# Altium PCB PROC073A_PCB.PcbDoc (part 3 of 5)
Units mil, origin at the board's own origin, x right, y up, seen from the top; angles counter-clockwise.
Board outline 2165.35 x 2165.35 mil, 6 copper layers (Top Layer, L2, L3, L4, L5, Bottom Layer), stack 55.77 mil thick; 284 components, 233 nets, 945 pads, 1419 vias.
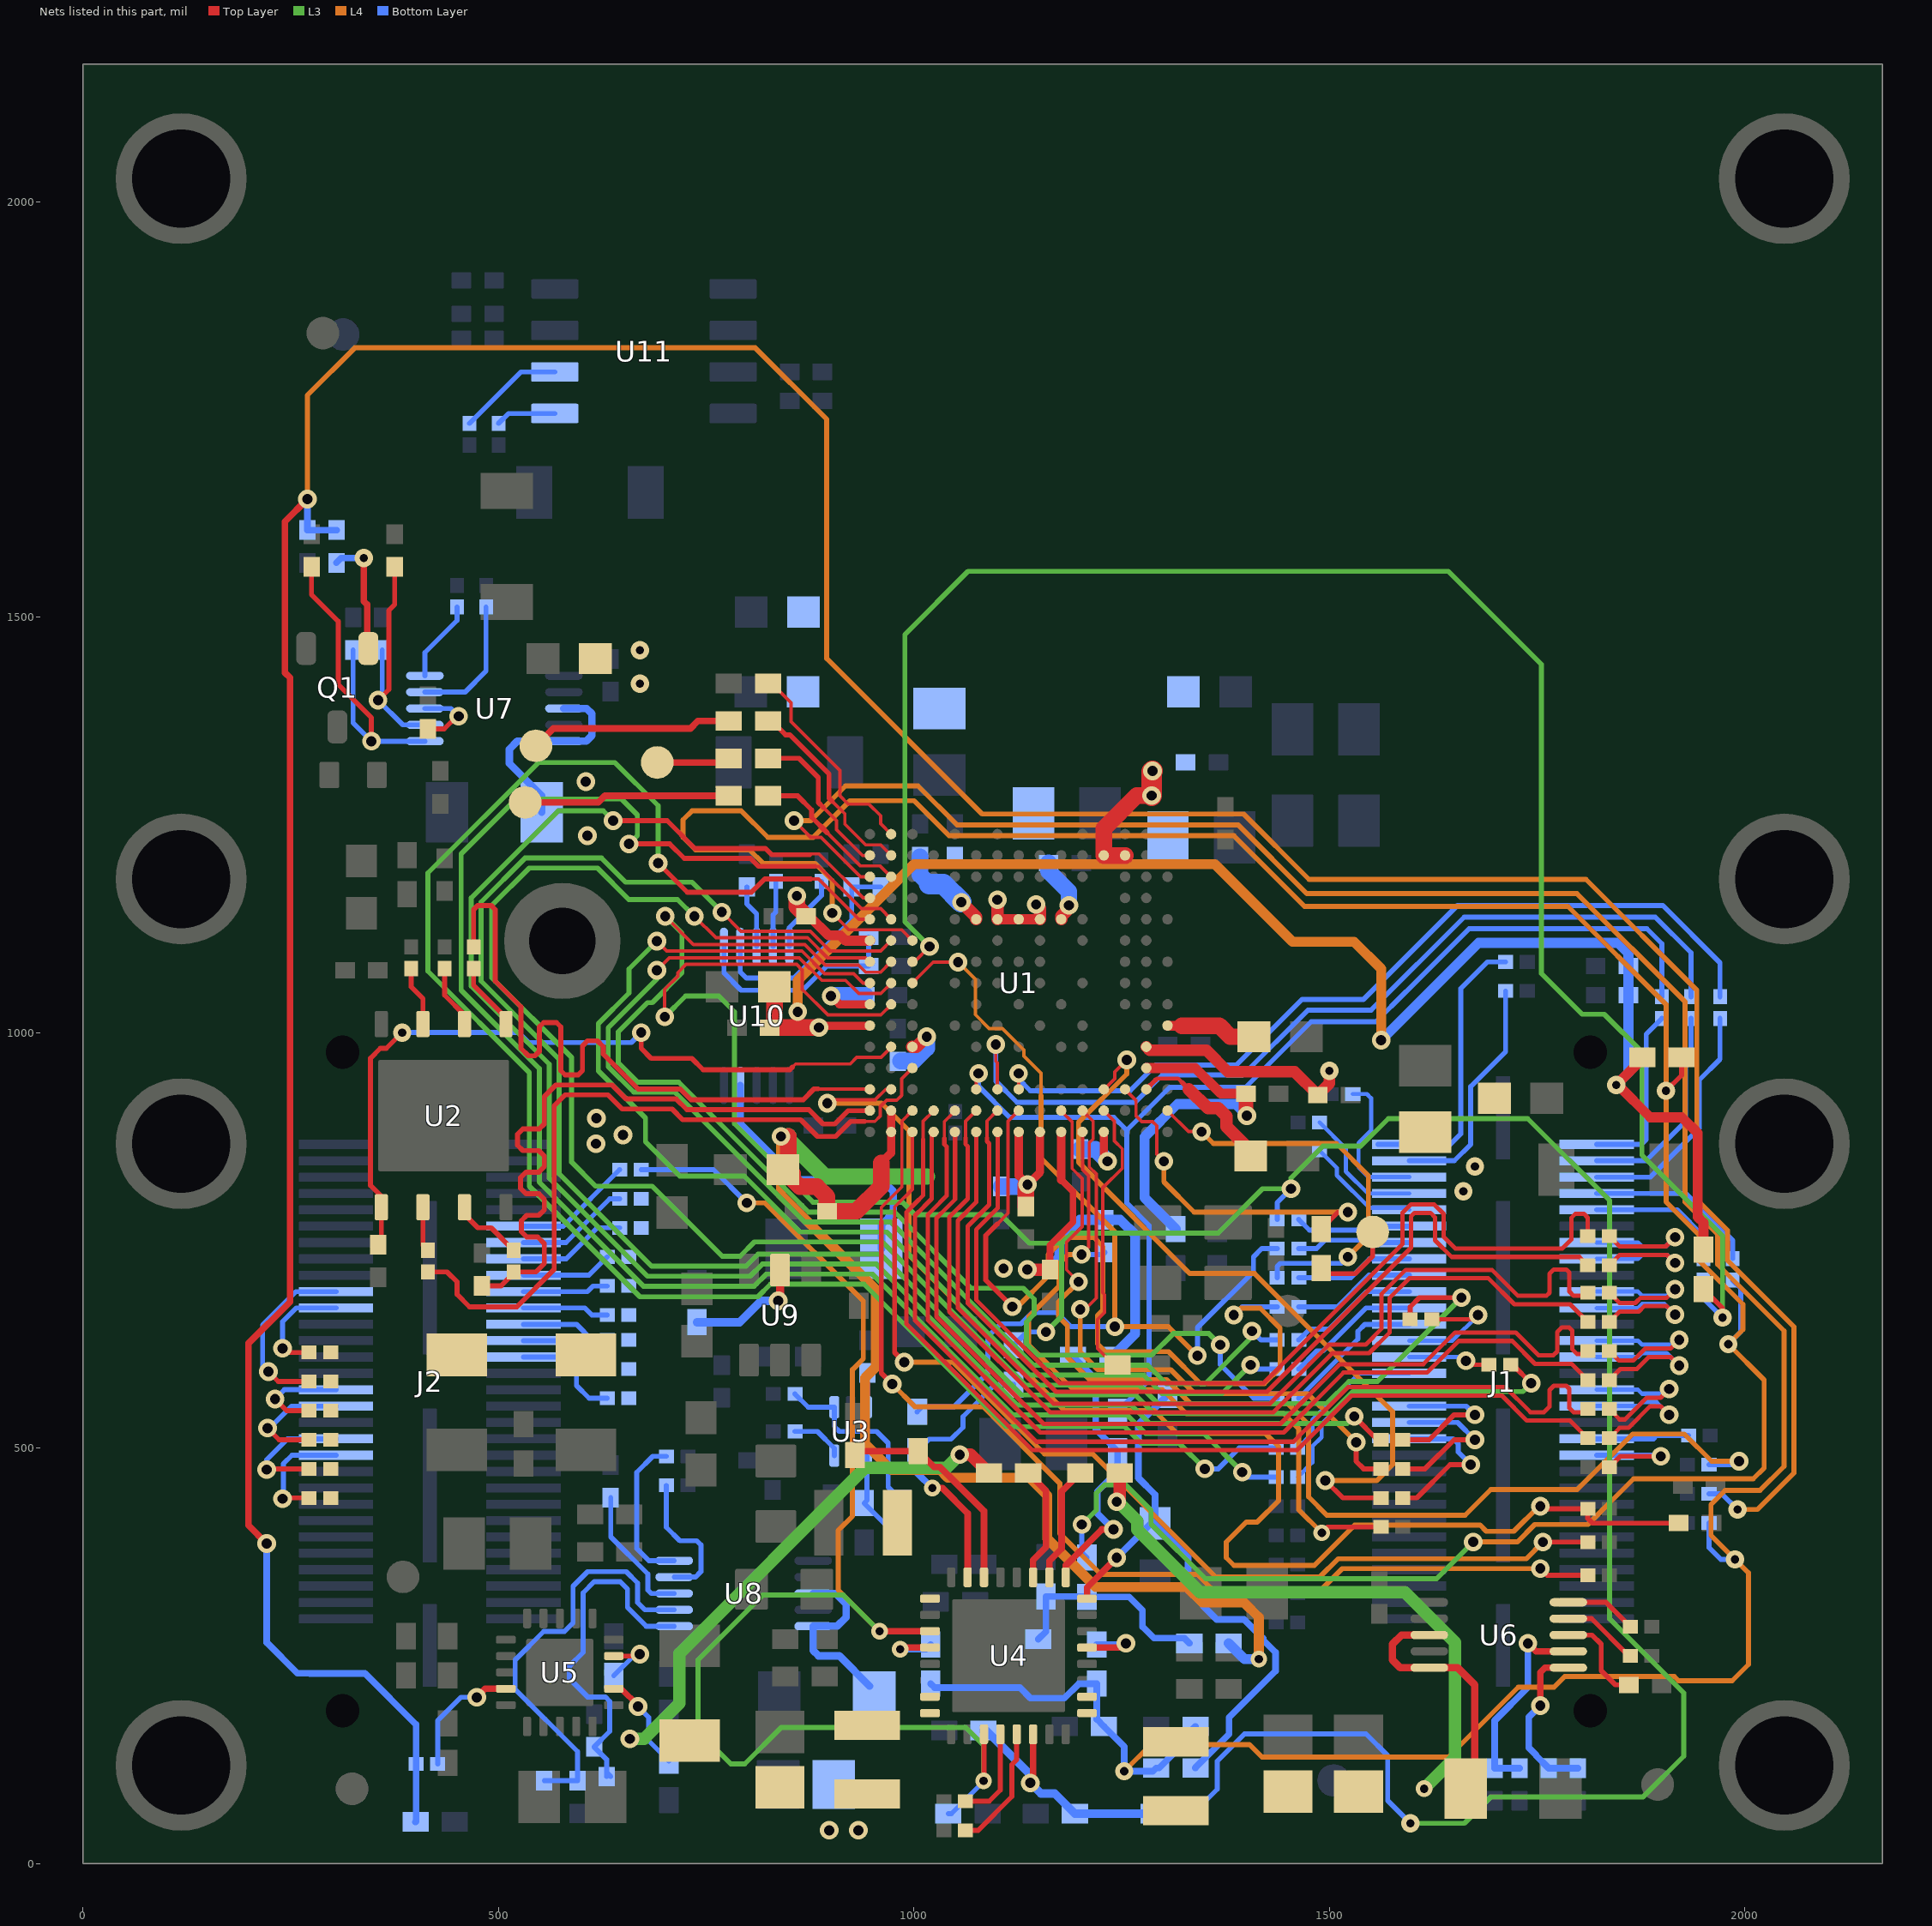
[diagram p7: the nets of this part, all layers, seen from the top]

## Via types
v1: diameter 13.77/15.74 (per signal layer), hole 5.9, Top Layer to L2, tented both sides, 894 vias
v2: diameter 22.4, hole 12.2, Top Layer to Bottom Layer, tented both sides, 340 vias
v3: diameter 13.78/15.75 (per signal layer), hole 5.9, Top Layer to L2, tented both sides, 72 vias
v4: diameter 22, hole 10, Top Layer to Bottom Layer, tented both sides, 54 vias
v5: diameter 20, hole 10, Top Layer to Bottom Layer, tented both sides, 35 vias
v6: diameter 13.77/15.74 (per signal layer), hole 5.9, Top Layer to L2, tented top, 14 vias
v7: diameter 19.68, hole 7.87, Top Layer to Bottom Layer, tented both sides, 9 vias
v8: diameter 13.78/15.75 (per signal layer), hole 5.9, Top Layer to L2, tented top, 1 vias

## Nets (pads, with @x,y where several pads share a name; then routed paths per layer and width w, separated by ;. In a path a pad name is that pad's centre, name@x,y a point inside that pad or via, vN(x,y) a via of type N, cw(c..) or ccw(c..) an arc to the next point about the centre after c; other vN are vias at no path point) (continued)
NetJ1_22: J1.22 R36.1 | length 145.2
  Top Layer w6: R36.1@1836.74,476.85 1849.89,490 v2(1898.74,490)
  Bottom Layer w6: J1.22@1821.54,491.42 1897.32,491.42 v2(1898.74,490)
NetJ1_23: J1.23 R11.2 | length 191.3
  Top Layer w6: R11.2@1587.99,440 1605,440 1645,480 v2(1670,480)
  Bottom Layer w6: J1.23@1595.95,511.1 1648.7,511.1 1654.8,505 1654.8,495.2 v2(1670,480)
NetJ1_24: J1.24 R16.1 | length 112.1
  Bottom Layer w6: J1.24@1821.54,511.1 1890,511.1 1893.9,515 R16.1@1932.01,515
NetJ1_25: J1.25 R12.1 | length 189.2
  Top Layer w6: R12.1@1587.99,475 1615,475 1650,510 v2(1675,510)
  Bottom Layer w6: J1.25@1595.95,530.79 1654.21,530.79 v2(1675,510)
NetJ1_27: J1.27 R18.2 | length 182.8
  Top Layer w6: R18.2@1587.99,510 1620,510 1650,540 v2(1675,540)
  Bottom Layer w6: J1.27@1595.95,550.47 1664.53,550.47 v2(1675,540)
NetJ1_28: J1.28 R22.1 | length 188
  Top Layer w5.2: R22.1@1836.74,511.85 1849.14,524.25 1859.78,524.25 1885.93,550.4 1898.47,550.4 v2(1908.87,540)
  Bottom Layer w5.2: J1.28@1821.54,550.47 1871.32,550.47 1876.07,555.21 1893.65,555.21 v2(1908.87,540)
NetJ1_29: J1.29 R19.2 | length 198.4
  Bottom Layer w5: R19.2@1461.74,465 1479.39,482.65 1479.39,501.82 1490.59,513.02 1490.59,529.01 1531.74,570.16 J1.29@1595.95,570.16
NetJ1_30: J1.30 R24.1 | length 184
  Top Layer w5.2: R24.1@1836.74,546.85 1849.14,534.45 1855.55,534.45 1881.7,560.6 1898.47,560.6 v2(1908.87,571)
  Bottom Layer w5.2: J1.30@1821.54,570.16 1871.32,570.16 1876.07,565.41 1903.28,565.41 v2(1908.87,571)
NetJ1_31: J1.31 R20.2 | length 180.8
  Bottom Layer w5: R20.2@1461.74,500 1479.39,517.65 1479.39,533.65 1535.58,589.84 J1.31@1595.95,589.84
NetJ1_33: J1.33 R21.2 | length 100
  Top Layer w5.2: v2(1664.21,605) 1669.22,600 R21.2@1692.01,600
  Bottom Layer w5: J1.33@1595.95,609.53 1659.69,609.53 v2(1664.21,605)
NetJ1_34: J1.34 R30.1 | length 207.5
  Top Layer w5.2: R30.1@1836.74,581.85 1850.02,595.13 1869.81,595.13 1884.22,609.55 1910.47,609.55 v2(1920.87,599.14)
  Bottom Layer w5.2: J1.34@1821.54,609.53 1871.32,609.53 1876.07,614.27 1905.74,614.27 v2(1920.87,599.14)
NetJ1_35: J1.35 R23.2 | length 153.4
  Top Layer w5.2: R23.2@1622.99,655 1673.74,655 v2(1678.74,660)
  Bottom Layer w5: J1.35@1595.95,629.21 1647.95,629.21 v2(1678.74,660)
NetJ1_36: J1.36 R32.1 | length 202.8
  Top Layer w5.2: R32.1@1836.74,616.85 1848.25,605.33 1865.59,605.33 1880,619.75 1910.47,619.75 v2(1920.87,630.14)
  Bottom Layer w5.2: J1.36@1821.54,629.21 1871.32,629.21 1876.07,624.47 1915.19,624.47 v2(1920.87,630.14)
NetJ1_37: J1.37 R26.2 | length 175.2
  Bottom Layer w6: R26.2@1462.99,560 1534.23,631.23 1534.23,640.48 1542.64,648.9 J1.37@1595.95,648.9
NetJ1_39: J1.39 R27.2 | length 163.4
  Bottom Layer w6: R27.2@1462.99,595 1484.92,616.93 1492.27,616.93 1543.92,668.58 J1.39@1595.95,668.58
NetJ1_40: J1.40 R33.1 | length 192.7
  Top Layer w5.2: R33.1@1836.74,651.85 1849.14,664.25 1872.17,664.25 1878.64,670.72 1905.79,670.72 v2(1915.87,660.65)
  Bottom Layer w5.2: J1.40@1821.54,668.58 1871.32,668.58 1876.07,673.32 1903.19,673.32 v2(1915.87,660.65)
NetJ1_41: J1.41 R28.2 | length 208.6
  Bottom Layer w5: 1544.74,688.01 1544.74,688.27 J1.41@1595.95,688.27
  Bottom Layer w6: R28.2@1462.99,630 1475.91,642.92 1499.23,642.92 1544.58,688.27 J1.41@1595.95,688.27
NetJ1_42: J1.42 R35.1 | length 190.5
  Top Layer w5.2: R35.1@1836.74,686.85 1849.14,674.45 1867.94,674.45 1870.05,676.56 1874.42,680.92 1905.79,680.92 v2(1915.87,691)
  Bottom Layer w5.2: J1.42@1821.54,688.27 1871.32,688.27 1876.07,683.52 1908.39,683.52 v2(1915.87,691)
NetJ1_43: J1.43 R60.1 | length 148.7
  Bottom Layer w6: R60.1@1462.99,670 1509.34,670 1547.29,707.95 J1.43@1595.95,707.95
NetJ1_45: J1.45 R61.1 | length 142.3
  Bottom Layer w6: R61.1@1462.99,705 1525.57,705 1548.21,727.64 J1.45@1595.95,727.64
NetJ1_46: J1.46 R39.1 | length 188.5
  Top Layer w5.2: R39.1@1836.74,720 1849.13,732.4 1906.26,732.4 v2(1915.87,722.8)
  Bottom Layer w5.2: J1.46@1821.54,727.64 1871.32,727.64 1876.07,732.38 1906.28,732.38 v2(1915.87,722.8)
NetJ1_47: J1.47 R62.1 | length 138.4
  Bottom Layer w6: R62.1@1462.99,740 1484.33,740 1494.53,750.2 1536.45,750.2 1539.33,747.32 J1.47@1595.95,747.32
NetJ1_48: J1.48 R41.1 | length 189.8
  Top Layer w5.2: R41.1@1836.74,755 1849.13,742.6 1904.67,742.6 v2(1915.87,753.8)
  Bottom Layer w5.2: J1.48@1821.54,747.32 1871.32,747.32 1876.07,742.58 1904.65,742.58 v2(1915.87,753.8)
NetJ1_49: J1.49 R63.1 | length 140.2
  Bottom Layer w6: R63.1@1462.99,775 1475.79,762.2 1538.17,762.2 1542.98,767.01 J1.49@1595.95,767.01
NetJ1_51: J1.51 R64.1 | length 142.9
  Bottom Layer w5: R64.1@1487.99,858 1508.75,837.24 1508.75,828.27 1547.74,789.28 1547.74,789 1593.64,789 J1.51@1595.95,786.69
NetJ1_52: J1.52 R58.1 | length 168.6
  Bottom Layer w6: J1.52@1821.54,786.69 1918.31,786.69 1950,755 R58.1@1950,727.99
NetJ1_53: J1.53 R34.2 | length 159.5
  Bottom Layer w5: R34.2@1487.99,892 1519.75,860.24 1519.75,832.83 1546.2,806.38 J1.53@1595.95,806.38
NetJ1_54: J1.54 R59.1 | length 208.8
  Bottom Layer w6: J1.54@1821.54,806.38 1928.62,806.38 1985,750 R59.1@1985,727.99
NetJ1_55: J1.55 R37.2 | length 179.1
  Bottom Layer w5: R37.2@1527.99,926 1545,926 1550,921 1550,882 1535,867 1535,838.06 1547,826.06 J1.55@1595.95,826.06
NetJ1_56: J1.56 R65.2 | length 290.2
  Bottom Layer w6: J1.56@1821.54,826.06 1886.06,826.06 1944.81,884.81 1944.81,942.79 1970,967.98 R65.2@1970,1017.01
NetJ1_57: J1.57 R38.2 | length 284.2
  Bottom Layer w5.98: J1.57@1595.95,845.75 1650.36,845.75 1670,865.39 1670,935 1712.01,977.01 R38.2@1712.01,1050
NetJ1_58: J1.58 R66.1 | length 253
  Bottom Layer w6: J1.58@1821.54,845.75 1880.86,845.75 1928.25,893.14 1928.25,968.32 1935,975.07 R66.1@1935,1017.01
NetJ1_59: J1.59 R40.2 | length 347.2
  Bottom Layer w5.98: J1.59@1558.31,865.43 1645.43,865.43 1658.01,878.01 1658.01,1053.01 1690,1085 R40.2@1712.01,1085
NetJ1_60: J1.60 R67.1 | length 215.6
  Bottom Layer w6: J1.60@1821.54,865.43 1875.43,865.43 1881.13,871.13 1881.13,998.14 R67.1@1900,1017.01
NetJ2_11: J2.11 R140.2 | length 143.9
  Bottom Layer w6: J2.11@530.04,767.01 577.76,767.01 R140.2@645.75,835
NetJ2_13: J2.13 R124.2 | length 137.5
  Bottom Layer w6: J2.13@530.04,747.32 581.07,747.32 633.74,800 R124.2@645.75,800
NetJ2_15: J2.15 R125.2 | length 131.2
  Bottom Layer w6: J2.15@530.04,727.64 581.38,727.64 618.74,765 R125.2@645.75,765
NetJ2_17: J2.17 R126.2 | length 109.8
  Bottom Layer w6: J2.17@530.04,707.95 608.7,707.95 R126.2@630.75,730
NetJ2_19: J2.19 R127.2 | length 103.5
  Bottom Layer w6: J2.19@530.04,688.27 607.01,688.27 613.74,695 R127.2@630.75,695
NetJ2_20: J2.20 R131.1 | length 218.2
  Top Layer w6: v2(223,592) 235,580 R131.1@272.01,580
  Bottom Layer w6: v2(223,592) 216,599 216,648.27 256,688.27 J2.20@304.44,688.27
NetJ2_21: J2.21 R128.2 | length 104.3
  Bottom Layer w6: J2.21@530.04,668.58 603.74,668.58 612.33,660 R128.2@630.75,660
NetJ2_22: J2.22 R133.1 | length 137.4
  Top Layer w6: v2(240,620) 245,615 R133.1@272.01,615
  Bottom Layer w6: v2(240,620) 240,652 256.58,668.58 J2.22@304.44,668.58
NetJ2_23: J2.23 R129.2 | length 108.5
  Bottom Layer w6: J2.23@530.04,648.9 593.74,648.9 612.64,630 R129.2@630.75,630
NetJ2_25: J2.25 R130.2 | length 114.9
  Bottom Layer w6: J2.25@530.04,629.21 583.67,629.21 617.88,595 R130.2@630.75,595
NetJ2_27: J2.27 R132.2 | length 135.7
  Bottom Layer w6: J2.27@530.04,609.53 584.21,609.53 593.74,600 593.74,575.29 609.03,560 R132.2@630.75,560
NetJ2_32: J2.32 R134.1 | length 124.9
  Top Layer w6: v2(231,559) 245,545 R134.1@272.01,545
  Bottom Layer w6: v2(231,559) 242.16,570.16 J2.32@304.44,570.16
NetJ2_34: J2.34 R135.1 | length 149.2
  Top Layer w6: v2(222,524) 236,510 R135.1@272.01,510
  Bottom Layer w6: v2(222,524) 224.57,524 251.04,550.47 J2.34@304.44,550.47
NetJ2_38: J2.38 R136.1 | length 157.3
  Top Layer w6: v2(221,474) 222,475 R136.1@272.01,475
  Bottom Layer w6: v2(221,474) 221,486 246,511 304.34,511 J2.38@304.44,511.1
NetJ2_40: J2.40 R137.1 | length 142.6
  Top Layer w6: v2(240,439) 241,440 R137.1@272.01,440
  Bottom Layer w6: v2(240,439) 241.2,440.2 241.2,481.2 251.42,491.42 J2.40@304.44,491.42
NetL4_1: L4.1 U4.25 U4.26
NetL5_1: L5.1 U4.15 U4.16
NetL6_2: L6.2 U4.9
NetQ1_1: Q1.1 R79.2 | length 146.3
  Top Layer w7.87: v4(338,1571) 338,1519 342,1515
  Top Layer w8: 342,1515 342,1463.64 Q1.1@343.4,1462.24
  Bottom Layer w7.87: R79.2@305,1565.31 310.68,1571 v4(338,1571)
NetR2_1: R2.1 R101.2 U6.2 | length 249.6
  Top Layer w8: v2(1738.74,265) 1748.43,255.31 U6.2@1787.4,255.32
  Bottom Layer w8: R2.1@1728.74,114.69 R101.2@1698.74,114.69 1698.74,172 1738.74,212 v2(1738.74,265)
NetR14_1: R14.1 R103.2 U6.1 | length 202
  Top Layer w8: v2(1753.74,190) 1753.74,230 1759.37,235.63 U6.1@1787.4,235.63
  Bottom Layer w8: v2(1753.74,190) 1739.8,176.06 1739.8,139.42 1748.58,130.64 1748.58,129.84 R14.1@1763.74,114.69 R103.2@1798.74,114.69
NetR25_1: R25.1 U6.5 | length 87.7
  Top Layer w6: U6.5@1788.03,315 U6.5@1787.4,314.37 1832.64,314.37 R25.1@1862.01,285
NetR29_1: R29.1 U6.4 | length 93.1
  Top Layer w6: U6.4@1787.4,294.69 1815.31,294.68 1860,250 R29.1@1862.01,250
NetR45_1: R45.1 U2.5 | length 82.9
  Top Layer w6: R45.1@470,1077.01 470,1057 509,1018 U2.5@509,1010.24
NetR46_2: R46.2 U2.2 | length 54.3
  Top Layer w6: U2.2@409,789.76 409,743.99 R46.2@415,737.99
NetR47_2: R47.2 U2.3 | length 85.6
  Top Layer w6: U2.3@459,789.76 459,781 475,765 490.99,765 R47.2@518,737.99
NetR48_1: R48.1 U2.6 | length 76.7
  Top Layer w6: R48.1@435,1077.01 435,1045 459,1021 U2.6@459,1010.24
NetR51_1: R51.1 U2.7 | length 72.6
  Top Layer w6: R51.1@395,1077.01 395,1055 409,1041 U2.7@409,1010.24
NetR54_1: R54.1 U3.3 | length 41.3
  Bottom Layer w6: U3.3@943.43,549.13 943.74,549.45 R54.1@943.74,590.32
NetR55_2: R55.2 U3.6 | length 64.6
  Bottom Layer w6: R55.2@856.74,520 883.74,520 904.06,499.68 U3.6@904.06,490.87
NetR56_2: R56.2 R151.1 U3.1 | length 229.3
  Bottom Layer w6: R56.2@856.74,565 872.6,549.13 U3.1@904.06,549.13 904.06,525.94 910,520 955,520 969,506 969,453 985,437 R151.1@985,433.62
NetR57_1: R57.1 R151.2 U3.4 | length 124.5
  Bottom Layer w6: U3.4@943.43,490.87 943.43,437.05 R57.1@940,433.62 985,388.62 R151.2@985,386.38
NetR69_1: R69.1 R122.2 R168.2 U4.32 | length 720.2
  Top Layer w8: U4.32@1208.23,318.9 1208.23,332.23 v2(1244,368)
  Bottom Layer w8: v2@1246.44,368 v2(1244,368) 1285.5,409.5 R122.2@1290,409.5 ; R69.1@1305,563.62 1270,528.62 1270,464 1290,444 R122.2@1290,409.5 ; R168.2@1338.62,115 1338.62,115.29 1379.17,155.83 1379.17,175.71 1435,231.54 1435,254.25 1420,269.25 1420,270.94 1397.17,293.77 1364.23,293.77 1329.91,328.09 1329.91,369.59 R122.2@1290,409.5
NetR72_2: R72.2 U1.P1 | length 260.2
  Top Layer w4.02: R72.2@824.21,1420 828.74,1420 851.87,1396.87 851.87,1374.3 910.74,1315.43 910.74,1285 920.91,1274.83 945.93,1274.83 959.85,1260.9 959.85,1251.33 U1.P1@972.43,1238.75 U1.P1@972.64,1238.54
NetR73_2: R73.2 U1.P2 | length 239.8
  Top Layer w4: 901.74,1278.18 916.74,1263.18 916.74,1250.8 941.73,1225.81 959.78,1225.81 U1.P2@972.64,1212.95
  Top Layer w6: R73.2@824.21,1375 828.74,1375 845.37,1358.37 850.59,1358.37 897.74,1311.22 897.74,1282.18 901.74,1278.18
NetR74_2: R74.2 U1.P3 | length 193.7
  Top Layer w4: 895.24,1240.71 935.43,1200.52 959.48,1200.52 U1.P3@972.43,1187.57
  Top Layer w6: R74.2@824.21,1285 824.41,1284.8 859.94,1284.8 876.74,1268 876.74,1259.2 895.24,1240.71
NetR75_2: R75.2 U1.R2 | length 195
  Top Layer w4.02: 890.74,1270.97 906.73,1254.98 906.73,1244.34 938.12,1212.95 U1.R2@947.05,1212.95
  Top Layer w6: R75.2@824.21,1330 861.57,1330 884.74,1306.83 884.74,1276.97 890.74,1270.97
NetR76_2: R76.2 U1.C13 | length 414.8
  Top Layer w4: U1.C13@1254.13,931.45 1267.08,918.51 1267.08,899.86 1274.08,892.86 1287.08,892.86 1292.08,887.86 1292.08,853.51 v2(1300.59,845)
  Top Layer w6: R76.2@1490,763.62 1510.38,784 v2(1522,784)
  L4 w6: v2(1300.59,845) 1300.59,820.41 1337,784 v2(1522,784)
NetR77_2: R77.2 U1.D14 | length 341.7
  Top Layer w4: U1.D14@1228.54,905.86 1241,893.41 1241,869.59 1250.59,860 1250.59,836.54 1227.29,813.24 1227.29,686.63 1229.29,684.63 1229.29,663 1220.74,654.45 1220.74,620 1240.74,600 R77.2@1245.12,600
NetR82_1: R82.1 U4.2 | length 140.9
  Top Layer w8: U4.2@1162.96,344.49 1162.95,364.21 1177.74,379 1177.74,447.62 R82.1@1200.12,470
NetR83_1: R83.1 U5.12 | length 119.5
  Top Layer w7: U5.12@638.7,210.32 647.83,210.31 667.74,190.4 v2(667.74,189)
  Bottom Layer w6: v2(667.74,189) 680.83,175.91 680.83,147.79 R83.1@705,123.62
NetR84_1: R84.1 U4.3 | length 140.8
  Top Layer w8: R84.1@1137.36,470 1158.74,448.62 1158.74,380.8 1143.27,365.33 U4.3@1143.27,344.49
NetR86_1: R86.1 R93.2 R97.1 R167.1 | length 262
  Bottom Layer w8: R167.1@1149.62,270 1158.74,279.12 R97.1@1158.74,321.38 R93.2@1207.72,321.38 ; R93.2@1208.23,320.87 1258.86,320.87 1274.94,304.78 1274.94,285.07 1288.82,271.2 1325.18,271.2 R86.1@1331.38,265
NetR87_1: R87.1 R98.2 U4.6 | length 265.7
  Top Layer w8: R87.1@931,489.38 938,496.38 R98.2@1005,496.38 1024.08,477.3 1031.13,477.3 1084.21,424.21 U4.6@1084.22,344.49
NetR88_2: R88.2 U4.21 | length 150.2
  Top Layer w6: R88.2@1061.74,40 1077.18,40 1117.74,80.57 1117.74,119.16 1123.59,125 U4.21@1123.59,155.51
NetR89_2: R89.2 U4.20 | length 114.8
  Top Layer w6: R89.2@1061.74,75 1090.43,75 1103.9,88.47 U4.20@1103.9,155.51
NetR90_1: R90.1 U4.29 | length 84.5
  Top Layer w8: U4.29@1208.23,259.84 1249.84,259.84 v2(1255,265)
  Bottom Layer w8: R90.1@1220,263.62 1253.62,263.62 v2(1255,265)
NetR91_1: R91.1 U4.12 | length 75.5
  Top Layer w8: v5(983.43,258) 985.27,259.84 U4.12@1019.25,259.84
  Bottom Layer w8: v5(983.43,258) 1014.38,258 R91.1@1020,263.62
NetR94_2: R94.2 U6.3 | length 116.5
  Top Layer w6: U6.3@1787.4,275 1816,275 1827,264 1827,232 1844,215 R94.2@1860.31,215
NetR100_2: R100.2 R102.2 R141.1 U4.22 | length 311.9
  Top Layer w8: v2(1140,97) 1143.27,100.27 U4.22@1143.27,155.51
  Bottom Layer w10: R100.2@1083.62,160 1087,160 1140,107 v2(1140,97) 1152.69,84.31 1169.31,84.31 R141.1@1193.62,60 R102.2@1288.38,60
NetR104_1: R104.1 R113.2 U7.2 | length 299.6
  Top Layer w6: v2(355,1400) 368,1413 368,1508 375,1515 R113.2@375,1560.31
  Bottom Layer w6: R104.1@360,1460.32 360,1405 v2(355,1400) 384.68,1370.31 U7.2@411.34,1370.31
NetR105_1: R105.1 R114.2 U7.1 | length 422.6
  Top Layer w6: R114.2@275,1560.31 275,1527 307,1495 307,1419 347,1379 v2(347,1350.63)
  Bottom Layer w6: R105.1@325,1460.32 325,1372.63 v2(347,1350.63) U7.1@411.34,1350.63
NetR106_1: R106.1 R116.2 U8.2 | length 510.2
  Bottom Layer w6: R116.2@555,99.69 R106.1@595,99.68 595,134.76 520,209.76 520,245 554.36,279.36 579.4,279.36 589.71,289.67 589.71,333.65 607.26,351.2 653.65,351.2 667.2,337.65 667.2,314.21 676.1,305.31 U8.2@711.34,305.31
NetR107_1: R107.1 R117.2 U8.1 | length 432
  Bottom Layer w6: R107.1@630,104.68 R107.1@630,109.68 ; R107.1@635,104.68 R107.1@630,109.68 ; U8.1@711.34,285.63 677.71,285.63 655.2,308.14 655.2,330.4 646.4,339.2 615.07,339.2 601.71,325.84 601.71,254.1 585.41,237.81 585.41,222.2 607.11,200.5 628.57,200.5 633.84,195.22 633.84,159.16 R117.2@615,140.31 630,125.31 R107.1@630,109.68
NetR108_1: R108.1 U7.5 | length 98.7
  Bottom Layer w6: U7.5@411.34,1429.37 411.34,1457.34 450,1496 R108.1@450,1512.01
NetR109_1: R109.1 U8.5 | length 186.4
  Bottom Layer w6: R109.1@702.01,490 685.63,490 666.3,470.67 666.3,379.15 681.08,364.37 U8.5@711.34,364.37
NetR110_1: R110.1 U7.4 | length 161.2
  Bottom Layer w6: U7.4@411.34,1409.68 459.68,1409.68 485,1435 R110.1@485,1512.01
NetR111_1: R111.1 U8.4 | length 167.8
  Bottom Layer w6: R111.1@702.01,455 702.01,404.65 718.26,388.4 738.64,388.4 743.54,383.5 743.54,351.34 736.88,344.68 U8.4@711.34,344.68
NetR112_2: R112.2 U7.3 | length 84.2
  Top Layer w6: R112.2@415,1365.31 434.68,1365.31 v2@450,1380.63
  Bottom Layer w6: U7.3@411.34,1390 442.63,1390 v2@450.8,1381.83
  other v2: 452,1380.63
NetR115_2: R115.2 U8.3 | length 163
  Bottom Layer w6: R115.2@635,440.31 635,393.03 679.7,348.33 679.7,329.18 683.88,325 U8.3@711.34,325
NetR119_2: R119.2 U9.5 | length 146.4
  Top Layer w10: v2(836.61,677.16) 838.74,679.29 U9.5@838.74,714.13
  Bottom Layer w10: R119.2@738.74,651.38 790.12,651.38 815.9,677.16 v2(836.61,677.16)
NetR121_2: R121.2 R165.2 U4.7 | length 341.2
  Top Layer w8: v5(1022,451.79) 1034.21,451.79 1064.53,421.47 U4.7@1064.53,344.49
  Bottom Layer w6: R121.2@1003.74,496.38 1018.08,510.71 1044.58,510.71 1058.87,525 1058.87,537.87 1097.38,576.38 R165.2@1120,576.38
  Bottom Layer w8: R121.2@1003.74,496.38 1003.74,470.05 v5(1022,451.79)
NetR139_1: R139.1 R146.2 U10.2 | length 272
  Bottom Layer w6: U10.2@790.91,1103.66 790.9,1073 798.4,1065.5 855.5,1065.5 925,1135 R146.2@925,1175.31 R139.1@960,1175.32
NetR142_1: R142.1 R147.2 U10.1 | length 261.6
  Bottom Layer w6: U10.1@771.22,1103.66 771.22,1071.78 792,1051 866,1051 895,1080 R147.2@945.31,1080 R142.1@945.32,1115
NetR143_1: R143.1 U10.5 | length 94.4
  Bottom Layer w6: U10.5@849.96,1103.66 849.96,1126.22 888.74,1165 R143.1@888.74,1182.01
NetR144_1: R144.1 U10.4 | length 79.8
  Bottom Layer w6: U10.4@830.28,1103.66 830.27,1141.53 833.74,1145 R144.1@833.74,1182.01
NetR145_2: R145.2 U10.3 | length 76.6
  Bottom Layer w6: R145.2@798.74,1175.32 798.74,1155 810.59,1143.15 U10.3@810.59,1103.66
NetR149_1: R149.1 U5.4 | length 149.9
  Top Layer w8: v2(473.74,200) 484.06,210.31 U5.4@508.78,210.32
  Bottom Layer w6: R149.1@426.73,120 426.73,171.99 454.74,200 v2(473.74,200)
NetR159_1: R159.1 U11.6 | length 128.4
  Bottom Layer w6: R159.1@465,1732.99 527.01,1795 U11.6@567.72,1795
NetR160_1: R160.1 U11.5 | length 72.7
  Bottom Layer w6: R160.1@500,1732.99 512.01,1745 U11.5@567.72,1745
NetR163_1: R163.1 U5.14 | length 74.3
  Top Layer w6: U5.14@638.7,249.69 667.69,249.69 v2(670,252)
  Bottom Layer w6: R163.1@638.7,226.06 664.64,252 v2(670,252)
PGOOD: R13.2 R79.1 R80.2 R148.1 R149.2 | length 4897.3
  Top Layer w8: v2(221,385) 199,407 199,626 249,676 249,1427 243,1433 243,1615 v2(270,1642)
  L4 w6: v2(270,1642) 270,1767 327,1824 809,1824 895,1738 895,1450 1082,1263 1396.59,1263 1475.27,1184.32 1808.68,1184.32 1942,1051 1942,798.94 1979,761.94 1979,725.97 2059,645.97 2059,470 2015,426 v4(1991,426)
  Bottom Layer w6: R13.2@1956.74,445 1972,445 v4(1991,426)
  Bottom Layer w8: v2(221,385) 221,266 258,229 273.02,229 273.22,228.8 339.2,228.8 400.75,167.25 400.75,50.63 R148.1@400.12,50 ; v2(270,1642) R80.2@270,1604.69 R79.1@305,1604.69
PMIC_1V0: R3.2 R68.2 R71.1 U7.8 U7.10 | length 260.9
  Bottom Layer w9: R71.1@552.09,1265 552.09,1284.91 513,1324 513,1341 522.63,1350.63 605.63,1350.63 612.3,1357.3 612.3,1383.7 606,1390 U7.8@578.66,1390
  other v2: 617.24,866.14 649.8,876.77 617.68,896.85 607,1237 605,1302
PMIC_1V8: C40.2 C41.1 L4.2 R70.1 R82.2 U6.8 U6.10 | length 1018.2
  Top Layer w9: U6.8@1620.08,275 1586.74,275 1575.74,264 1575.74,245 1585.11,235.63 1654.11,235.63 1674.74,215 1674.74,101 R70.1@1663.74,90
  Top Layer w15: v2@1247.36,435.38 R82.2@1247.37,470
  L3 w15: v2(1244,435.38) 1245.55,435.38 1268.7,412.23 1268.7,401.77 1344.17,326.3 1590.7,326.3 1651,266 1651,127.26 v5(1613.74,90)
PMIC_1V24: C46.1 C47.1 L5.2 R81.1 R84.2 R96.1 U8.8 U8.10 | length 838.2
  Top Layer w15: v2(1055,492) 1068.12,492 R84.2@1090.12,470
  L3 w15: v2(658,150) 675.09,150 717.85,192.76 717.85,252.85 941,476 1039,476 v2(1055,492)
  Bottom Layer w9: U8.8@878.66,325 905.95,325 918.31,312.64 918.31,296.29 907.65,285.63 U8.10@878.66,285.63 878.66,256.34 885,250 910,250 R96.1@946.5,213.5
  other v2: 898,40 933,40
PMIC_EN: R118.1 R140.1 U4.11 U4.19 | length 1723.7
  Top Layer w6: v5(1083.74,99.49) 1084.22,99.96 U4.19@1084.22,155.51
  Top Layer w8: v5(958.43,279.53) U4.11@1019.25,279.53
  L3 w6: v5(958.43,279.53) 914.95,323 818,323 740,245 740,159.43 779.63,119.8 796.37,119.8 840.44,163.87 1062.08,163.87 1083.74,142.2 v5(1083.74,99.49)
  L4 w6: v2(798.74,795) 820.68,795 938.89,676.8 938.89,607.34 925.98,594.43 925.98,418.05 908.66,400.73 908.66,329.29 v5(958.43,279.53)
  Bottom Layer w6: R140.1@671.74,835 758.74,835 v2(798.74,795) ; R118.1@1041.38,60 1045,60 1083.74,98.74 v5(1083.74,99.49)
RADAR_1P0_RF1: C19.2 C23.2 L3.2 U1.G5 U1.H5 U1.J5 | length 94.3
  Top Layer w12: U1.J5@1100.39,1136.39 U1.G5@1151.57,1136.39
  Top Layer w15: U1.J5@1100.39,1136.39 v2(1100.38,1159.9) ; v2(1146.87,1154.07) 1151.56,1149.38 U1.G5@1151.57,1136.39
RADAR_1P0_RF2: C20.2 C24.2 L2.2 R1.1 U1.C2 U1.D2 | length 162.3
  Top Layer w20: U1.C2@1254.13,1212.95 1228.54,1212.95 1228.54,1245.73 1268.02,1285.21 v2(1285.98,1285.21)
  Top Layer w25: v2(1285.98,1285.21) 1285.98,1313.96 v2(1286.98,1314.96)
RADAR_1V2: C25.2 C26.2 C27.2 C28.2 C29.2 C30.1 L7.2 R86.2 U1.G15 U1.H15 U1.N11 U1.P14 U1.P15 U1.R6 | length 1987.3
  Top Layer w10: 960.59,843.15 972.43,855 U1.P14@972.43,906.07 ; U1.H15@1125.98,880.48 1125.97,827.62 1135.59,818 v2(1136.52,817.07) 1151.56,832.11 U1.G15@1151.57,880.48
  Top Layer w12: C28.2@870.28,1140 874.13,1140 897.27,1116.86 911.08,1116.86 917.08,1110.86 918.08,1110.86 ; 918.35,1110.59 U1.R6@947.05,1110.59
  Top Layer w15: U1.N11@998.03,982.84 1003.1,982.85 v2(1015.27,995.02)
  Top Layer w20: C27.2@842.09,835 C27.2@850.41,826.67 ; v2@848.74,875 848.74,835 853.74,830 C27.2@850.41,826.67 ; v2(858.92,1164.5) 858.92,1151.35 C28.2@870.28,1140 ; 960.59,843.15 960.59,815 930.59,785 C25.2@895.28,785 895.27,802.53 883.27,814.53 862.55,814.53 C27.2@850.41,826.67 ; C26.2@1134.5,790.69 1134.5,816.91 v2@1135.59,818
  L3 w20: v2@848.74,875 848.74,870.53 892.48,826.8 1015.2,826.8
  L4 w12: v2(840,875) 840,804.55 953.89,690.66 953.89,597.23 940.98,584.32 940.98,505.3 972.49,473.79 1031.11,473.79 1040.44,464.46 1138.87,464.46 1160.43,442.9 1160.43,390.98 1218.61,332.8 1328.17,332.8 1346.92,314.05 1397.24,314.05 1415,296.29 v5(1415,245.97)
  Bottom Layer w12: R86.2@1378.62,265 1397.65,245.97 v5(1415,245.97)
  Bottom Layer w20: C29.2@983.87,965.77 999.57,965.77 1015.27,981.47 v2(1015.27,995.02) ; C30.1@1105,814.68 v2@1129.04,814.68
  other v4: 670,1420 670,1460
RADAR_1V4_APLL: C22.2 U1.A10 | length 109.3
  Top Layer w12: U1.A10@1305.31,1008.23 1322.36,1008.23
  Top Layer w20: 1322.36,1008.23 1367.36,1008.23 1380.59,995 C22.2@1409.09,995
RADAR_1V4_SYNTH: C18.2 U1.B13 | length 201.1
  Top Layer w4.5: 1290.62,942.76 1292.6,944.75 1317.84,944.75 1322.59,940
  Top Layer w6: U1.B13@1279.52,931.66 1290.62,942.76 ; 1322.59,940 1330.7,931.88
  Top Layer w15: 1330.7,931.88 1353.7,908.89 1366.11,908.89 1375.89,899.11 1375.89,886.7 1397.03,865.56 C18.2@1397.03,863.71 ; C18.2@1397.03,863.71 1405.28,855.45 C18.2@1405.28,851.41 1397.03,851.41 C18.2@1397.03,863.71
RADAR_1V8: C5.2 C9.2 C10.2 C11.2 C12.2 C13.2 C14.2 C15.2 L1.2 R166.1 U1.B11 U1.B12 U1.D15 U1.F5 U1.K5 U1.R9 | length 1059.4
  Top Layer w10: v2(900.17,1044.07) 910.21,1034.03 U1.R9@946.84,1034.03 ; U1.D15@1228.54,880.27 1228.54,849.4 v2(1232.87,845.07)
  Top Layer w12: U1.B12@1279.52,957.25 1338.33,957.26 1369.18,926.41 C5.2@1399.5,926.41 ; v2@1399.5,901.09 v2(1400.59,900)
  Top Layer w14: U1.B11@1279.52,982.84 1283.49,978.87 1351.72,978.87 1377.59,953 1457.9,953 C14.2@1485.91,925 1500,939.09 v4(1500,954)
  Top Layer w15: v2(1057,1156.84) 1074.79,1139.05 U1.K5@1074.8,1136.39 ; U1.F5@1177.16,1136.39 1177.15,1140.35 1183.87,1147.07 1183.87,1149.06 1186.34,1151.53 v2(1186.34,1153.07)
  Top Layer w18: v2@1399.5,901.09 C5.2@1399.5,926.41
  Bottom Layer w12: R166.1@1315,763.62 1277.39,801.23 1277.39,874.39 1317,914 1386.59,914 v2(1400.59,900)
  Bottom Layer w20: v2(900.17,1044.07) 901.1,1045 C10.2@940.91,1045 ; C11.2@1007.18,1211.72 1007.18,1189.82 1018.43,1178.57 ; C12.2@1161.91,1204 1161.67,1203.77 1161.67,1194.32 1186.34,1169.65 v2(1186.34,1153.07) ; C9.2@1200,859.69 1218.26,859.68 v2(1232.87,845.07)
  Bottom Layer w25: 1018.43,1178.57 1035.27,1178.57 v2(1057,1156.84)
  other v4: 1661,809 1675,839
RADAR_3V3: C16.2 C17.2 C21.2 R123.2 R150.2 R153.2 R154.2 R156.2 R169.2 R170.2 U1.F15 U1.R10 U10.9 | length 2817.3
  Top Layer w8: C16.2@1163.59,714.69 1163.59,744 1191.29,771.7 1191.29,808.57 1177.15,822.71
  Top Layer w10: v2(885.58,1006.06) 887.75,1008.23 U1.R10@947.05,1008.23 ; 1177.15,822.71 U1.F15@1177.16,880.48
  Top Layer w12: R169.2@1876.38,970 1876.38,968.38 v4(1845,937) 1847.03,937 1886.11,897.91 1924.09,897.91 1943,879 1943,778 1950,771 R150.2@1950,738.62
  Top Layer w15: v2(1136.27,714.68) C16.2@1163.59,714.69
  Top Layer w20: C17.2@832.09,1055 832.09,1011.81 C21.2@826.28,1006 885.52,1006 v2(885.58,1006.06)
  L4 w12: v2(860,1025) 860,1062.94 999.84,1202.78 1362.06,1202.78 1455.66,1109.18 1529.55,1109.18 1562.17,1076.56 v2(1562.17,990.81)
  Bottom Layer w9: U10.9@790.91,936.34 790.9,890 857.9,823 961,823 975,809 975,783 960.83,768.82 R123.2@960.83,740
  Bottom Layer w12: v2(1136.27,714.68) 1159.68,714.68 1175,730 1175,750 1199.68,774.68 R156.2@1230,774.69 1248,774.69 1266,756.69 1266,637.38 R170.2@1238.62,610 ; v2(1562.17,990.81) 1679.36,1108 1847,1108 1859.68,1095.31 1859.68,951.68 v4(1845,937)
  other v2: 1107.74,716
RADAR_ANAMUX: R76.1 TP6.1 | length 105.5
  Top Layer w6: R76.1@1490,719.31 R76.1@1490,716.38 1496.58,709.8 1530.98,709.8 1552,730.82 TP6.1@1552,760
RADAR_ANATEST2: R73.1 TP3.1 | length 244.4
  Top Layer w8: TP3.1@545,1345 566,1366 731,1366 740,1375 R73.1@776.97,1375
RADAR_ANATEST3: R74.1 TP4.1 | length 248.3
  Top Layer w8: TP4.1@532,1277 620,1277 628,1285 R74.1@776.97,1285
RADAR_ANATEST4: R75.1 TP5.1 | length 88
  Top Layer w8: TP5.1@691,1325 771.97,1325 R75.1@776.97,1330
RADAR_BSS_LOGGER: R60.2 U1.H14 | length 969.3
  Top Layer w4: 1100.16,769.57 1113.18,782.59 1113.18,893.29 U1.H14@1125.98,906.07
  Top Layer w6: 1100.11,769.62 1086.39,755.9 1086.39,702.08 v2(1118.38,670.09)
  L4 w6: v2(1118.38,670.09) 1124.7,670.09 1161.71,707.1 1161.71,732.97 1181.94,753.2 1216.71,753.2 1227.22,742.69 1227.22,666.03 1220.81,659.62 1220.81,625.43 1230.3,615.94 1306.29,615.94 1344.75,577.48 1421.64,577.48 1440.56,596.4 1440.56,644.37 1416.53,668.4 1393.23,668.4 v2(1384.83,660)
  Bottom Layer w6: v2(1384.83,660) 1394.83,670 R60.2@1437.01,670
RADAR_CS1: R7.1 R156.1 U1.E15 | length 905.6
  Top Layer w4: v2(1201.59,733) 1210.29,741.7 1210.29,827.66 1202.95,835 U1.E15@1202.95,880.27
  Top Layer w6: v5(1490.74,398) 1497.74,405 R7.1@1562.01,405
  L4 w6: v2(1201.59,733) 1185.48,733 1174.28,721.8 1174.28,694.27 1138.2,658.2 1138.2,623.78 1191.59,570.39 1298.88,570.39 1327.76,541.51 1444.89,541.51 1462.81,523.58 1462.81,425.93 v5(1490.74,398)
  Bottom Layer w6: v2(1201.59,733) 1227.68,733 R156.1@1230,735.32
RADAR_DMM_CLK: R15.1 U1.N15 | length 1237.8
  Top Layer w4: 976.59,775 976.59,790 998.02,811.43 U1.N15@998.03,880.48
  Top Layer w6: 976.59,775 976.59,614.9 v2(988.18,603.31) ; v2(1756.89,386.85) R15.1@1810.75,386.85
  L4 w6: v2(988.18,603.31) 1046.69,603.31 1157.08,492.92 1215.02,492.92 1362.94,345 1488.57,345 1510.37,366.8 1736.85,366.8 v2(1756.89,386.85)
RADAR_DMM_SYNC: R17.1 U1.N14 | length 1338.4
  Top Layer w4: 960.59,772.38 960.59,789.54 985.43,814.39 985.43,860.59 985.47,860.63 985.47,893.53 U1.N14@998.03,906.07
  Top Layer w6: 960.59,772.38 960.59,590.15 v2(973.74,577) ; v2(1753.74,355) 1761.89,346.85 R17.1@1810.75,346.85
  L4 w6: v2(973.74,577) 1000.94,549.8 1083.23,549.8 1175.43,457.6 1175.43,397.19 1224.82,347.8 1340.98,347.8 1358.7,330.08 1490.62,330.08 1515.34,354.8 1753.54,354.8 v2(1753.74,355)
RADAR_DP0: R18.1 U1.R4 | length 2092.6
  Top Layer w4: 875.43,1215 885.59,1215 938.61,1161.98 U1.R4@946.84,1161.98
  Top Layer w6: v2(638,1255) 702.81,1255 736.28,1221.54 821.2,1221.54 828.74,1214 874.43,1214 ; v2(1529.74,538) 1557.74,510 R18.1@1562.01,510
  L3 w6: v2(638,1255) 626,1267 572,1267 467,1162 467,1055.85 561,961.85 561,825.03 679.23,706.8 802.8,706.8 817.37,721.36 954.75,721.36 1124.31,551.81 1261.39,551.81 1283.56,529.64 1521.38,529.64 v2(1529.74,538)
RADAR_DP1: R19.1 U1.P5 | length 2119.1
  Top Layer w4: 880.59,1200 885.59,1200 936.52,1149.07 959.75,1149.07 U1.P5@972.43,1136.39
  Top Layer w6: v2(657,1227) 706,1227 723.46,1209.54 803.2,1209.54 812.74,1200 880.59,1200
  L3 w6: v2(657,1227) 667,1237 667,1262 648,1281 520.97,1281 455,1215.03 455,1050.88 549,956.88 549,820.06 674.26,694.8 807.77,694.8 822.34,709.36 949.78,709.36 1119.34,539.81 1256.42,539.81 1278.59,517.64 1348.36,517.64 v2(1395,471)
  Bottom Layer w6: v2(1395,471) 1401,465 R19.1@1435.75,465
RADAR_DP2: R20.1 U1.R5 | length 2209.3
  Top Layer w4: 875.59,1185 884.86,1185 933.68,1136.18 U1.R5@947.05,1136.18
  Top Layer w6: v2(692,1204) 727.2,1168.8 804.39,1168.8 820.59,1185 875.59,1185
  L3 w6: v2(692,1204) 692,1273 640,1325 548,1325 415,1192 415,1073.91 537,951.91 537,815.09 670.07,682.01 811.96,682.01 827.31,697.36 939.66,697.36 1111.27,525.76 1253.5,525.76 1273.62,505.64 1319.36,505.64 v2(1350,475)
  Bottom Layer w6: v2(1350,475) 1366.2,475 1391.2,500 R20.1@1435.75,500
RADAR_DP3: R21.1 U1.P6 | length 2283.1
  Top Layer w4: v2(768.74,1145) 791.74,1122 875.16,1122 899.09,1098.07 959.7,1098.07 U1.P6@972.43,1110.8
  Top Layer w6: R21.1@1717.99,600 1720.74,600 v2(1742.73,578)
  L3 w6: v2(768.74,1145) 732.74,1181 652.96,1181 623.97,1209.99 531.96,1209.99 479,1157.03 479,1062 573,968 573,830 684.2,718.8 797.83,718.8 812.4,733.36 959.72,733.36 1129.28,563.81 1136.91,563.81 1266.36,563.81 1288.53,541.64 1501.83,541.64 1528.19,568 1732.74,568 v2(1742.73,578)
RADAR_DP4: R23.1 U1.R7 | length 2208.2
  Top Layer w4: v2(735.59,1140) 761.59,1114 871.84,1114 895.78,1090.07 941.98,1090.07 U1.R7@946.84,1085.21
  Top Layer w5.98: R23.1@1597.01,655 1597.01,669.82 1608.19,681 1610,681
  Top Layer w6: 1610,681 v2(1658.74,681)
  L3 w5.98: v2(735.59,1140) 715.4,1160.19 656.81,1160.19 619,1198 536.93,1198 492,1153.07 492,1065.96 588,969.96 588,844 616.81,815.19 684.87,815.19 769.27,730.79 790.61,730.79 807.81,747.99 962.06,747.99 1134.24,575.8 1174.41,575.8 1271.33,575.8 1293.5,553.63 1496.86,553.63 1523.22,579.99 1557.74,579.99 v2(1658.74,681)
RADAR_DP5: R26.1 U1.P7 | length 1565
  Top Layer w4: v2(700.59,1140) 734.59,1106 868.53,1106 893.46,1081.07 933.27,1081.07 941.67,1072.67 959.89,1072.67 U1.P7@972.43,1085.21
  L3 w5.98: v2(700.59,1140) 720.79,1119.79 720.79,1071.79 685,1036 679.18,1036 643.98,1000.8 643.98,963.91 667.59,940.3 716.95,940.3 873.3,783.94 976.96,783.94 1068.49,692.41 1131.42,692.41 1144.64,679.18 1144.64,661.01 1135.3,651.66 1135.3,625.6 1149.12,611.78
  L3 w6: 1149.12,611.78 1286.02,611.78 1311.98,637.74 1354.93,637.74 v2(1368.44,624.23)
  Bottom Layer w6: v2(1368.44,624.23) 1368.44,600.49 1408.93,560 R26.1@1437.01,560
RADAR_DP6: R27.1 U1.R8 | length 1479.3
  Top Layer w4: v2(690.59,1110) 702.59,1098 865.22,1098 892.36,1070.86 927.48,1070.86 938.72,1059.62 U1.R8@946.84,1059.62
  L3 w5.98: v2(690.59,1110) 657,1076.41 657,1047.71 620.01,1010.73 620.01,953.98 676.89,897.11 676.89,868.42 718.13,827.18 795.66,827.18 862.87,759.97 967.02,759.97 1139.21,587.79 1179.37,587.79 1276.29,587.79 1298.46,565.62 1370.62,565.62 v2(1405,600) v2@1405,606
  Bottom Layer w5.98: v2(1405,600) 1410,595 R27.1@1437.01,595
RADAR_DP7: R28.1 U1.P8 | length 1449.2
  Top Layer w4: v2(690.59,1075) 705.59,1090 861.9,1090 889.04,1062.86 917.42,1062.86 933.37,1046.91 960.14,1046.91 U1.P8@972.64,1059.41
  L3 w5.98: v2(690.59,1075) 690.59,1064.35 632,1005.76 632,958.95 662.63,928.32 711.98,928.32 868.34,771.96 971.98,771.96 1144.17,599.77 1184.34,599.77
  L3 w6: 1184.34,599.78 1281.26,599.78 1303.43,577.61 1350.39,577.61 1406.71,633.93 v2(1406.71,640.8)
  Bottom Layer w6: v2(1406.71,640.8) 1417.51,630 R28.1@1437.01,630
RADAR_DP8: R124.1
RADAR_DP9: R125.1
RADAR_DP10: R126.1
RADAR_DP11: R127.1
RADAR_DP12: R128.1
RADAR_DP13: R129.1
RADAR_DP14: R130.1
RADAR_DP15: R132.1
RADAR_GPIO_0: R65.1 U1.H13 | length 1037.9
  Top Layer w4: v2(1125.87,950.86) 1125.97,950.76 U1.H13@1125.98,931.66
  Bottom Layer w6: v2(1125.87,950.86) 1125.87,944.12 1139.97,930.03 1260.03,930.03 1290.94,960.94 1387.94,960.94 1467,1040 1541,1040 1654,1153 1901,1153 1970,1084 R65.1@1970,1042.99
RADAR_GPIO_1: R66.2 U1.J13 | length 1109.2
  Top Layer w4: v2(1098.42,985.66) 1098.42,965.46 1100.38,963.5 U1.J13@1100.39,931.66
  Bottom Layer w6: v2(1098.42,985.66) 1098.42,941.57 1124,916 1266,916 1298.94,948.94 1395.94,948.94 1474,1027 1550,1027 1662,1139 1892,1139 1935,1096 R66.2@1935,1042.99
RADAR_GPIO_2: R67.2 R171.2 U1.K13 | length 1417.7
  Top Layer w4: U1.K13@1074.8,931.66 1074.79,947.94 v2(1077.67,950.82)
  Bottom Layer w6: v2(1077.67,950.82) 1077.67,935.33 1115,898 1240.43,898 1256,882.43 ; R171.2@1245,543.62 1283,581.62 1283,768 1256,795 1256,882.43 ; R67.2@1900,1042.99 1900,1107 1882,1125 1668,1125 1592,1049 1591.79,1049 1555.79,1013 1478,1013 1399,934 1307.57,934 1256,882.43
RADAR_HOSTINTR1: R10.2 R152.2 U1.P13 | length 1652.8
  Top Layer w4: v2(895.59,915) 899.55,918.95 953.35,918.95 965.85,931.45 U1.P13@972.64,931.45
  Top Layer w6: v2(1753.74,430) 1756.89,426.85 R10.2@1810.75,426.85 1810.75,415.29 1816.46,409.58 1919.9,409.58 R152.2@1920.31,410
  L4 w6: v2(895.59,915) 960.87,915 994,881.87 994,732 1180.99,545.01 1288.96,545.01 1316.44,517.53 1422.93,517.53 1438.83,501.62 1438.83,436.79 1413.04,411 1400,411 1375.8,386.8 1375.8,368 1385,358.8 1481.8,358.8 1530.2,407.2 1681.37,407.2 1688.77,399.8 1721.83,399.8 1752.03,430 v2(1753.74,430)
RADAR_INTn: R170.1 R171.1 U4.1 | length 337.7
  Top Layer w8: U4.1@1182.64,344.49 1182.64,358.66 1225.98,402 v2(1240,402)
  Bottom Layer w8: R170.1@1191.38,610 1218.74,582.64 1218.74,522.64 R171.1@1245,496.38 1245,472 1220.78,447.78 1220.78,421.22 v2(1240,402)
RADAR_LVDS_0M: R41.2 U1.J15 | length 1196.4
  Top Layer w5.2: U1.J15@1100.59,880.27 1100.59,788.57 1074.79,762.77 1074.79,678.38 1175.17,578 1420.51,578 1587.89,745.38 1587.89,783.2 1597.97,793.28 1625.8,793.28 1637.25,781.83 1637.25,754.17 1651.22,740.2 1780.2,740.2 1791,751 1791,777 1796,782 1806,782 1810.75,777.25 R41.2@1810.75,755
RADAR_LVDS_0P: R39.2 U1.J14 | length 1192.7
  Top Layer w4: 1087.88,873.07 1087.88,893.58 U1.J14@1100.39,906.07
  Top Layer w5.2: 1087.88,873.07 1087.88,869.06 1090.39,866.55 1090.39,792.8 1064.59,767 1064.59,674.15 1170.94,567.8 1424.74,567.8 1598.09,741.15 1598.09,778.97 1602.2,783.08 1621.58,783.08 1627.05,777.61 1627.05,749.94 1646.99,730 1800.68,730 1800.71,730.03 R39.2@1810.75,720
RADAR_LVDS_1M: R35.2 U1.K15 | length 1185.9
  Top Layer w5.2: U1.K15@1074.8,880.48 1074.79,795.78 1052.73,773.71 1052.73,668.5 1168.02,553.2 1428.16,553.2 1499.29,624.34 1543.35,624.34 1562.37,643.35 1562.37,685.1 1591.77,714.5 1695.45,714.5 1726.75,683.2 1761.04,683.2 1764.8,686.96 1764.8,709.8 1770,715 1785,715 1788.6,711.4 1788.6,688.4 1793.8,683.2 1807.1,683.2 R35.2@1810.75,686.85
RADAR_LVDS_1P: R33.2 U1.K14 | length 1188.9
  Top Layer w4: 1061.87,873.07 1061.87,893.16 U1.K14@1074.8,906.07
  Top Layer w5.2: 1061.87,873.07 1061.87,865.77 1064.59,863.05 1064.59,800 1062.48,797.89 1042.53,777.94 1042.53,664.27 1163.8,543 1432.38,543 1503.52,614.14 1547.58,614.14 1572.57,639.13 1572.57,680.87 1595.99,704.3 1691.23,704.3 1722.53,673 1789.6,673 R33.2@1810.75,651.85
RADAR_LVDS_2M: R137.2
RADAR_LVDS_2P: R136.2
RADAR_LVDS_3M: R135.2
RADAR_LVDS_3P: R134.2
RADAR_LVDS_CLKM: R32.2 U1.L15 | length 1181.1
  Top Layer w5.2: U1.L15@1049.41,880.27 1049.41,862.85 1049.4,799.23 1032.33,782.16 1032.33,782.06 1026.99,776.72 1026.99,658.01 1156,529 1440.67,529 1512.59,600.93 1612.95,600.93 1651.09,639.07 1724.05,639.07 1751.55,611.57 1769.27,611.57 1774.01,616.3 1774.01,639.58 1779.58,645.15 1788.4,645.15 1792,641.55 1792,619.06 1797.71,613.35 1807.25,613.35 R32.2@1810.75,616.85
RADAR_LVDS_CLKP: R30.2 U1.L14 | length 1182.8
  Top Layer w4: 1036.49,872.85 1036.49,892.94 U1.L14@1049.41,905.86
  Top Layer w5.2: 1036.49,872.85 1036.49,865.55 1039.2,862.84 1039.2,803.46 1022.13,786.39 1022.13,786.29 1016.79,780.95 1016.79,653.79 1151.78,518.8 1444.89,518.8 1516.82,590.73 1617.18,590.73 1655.32,628.87 1719.82,628.87 1747.33,601.37 1791.23,601.37 R30.2@1810.75,581.85
RADAR_LVDS_FRCLKM: R24.2 U1.M15 | length 1198.8
  Top Layer w5.2: U1.M15@1023.82,880.27 1021.27,877.73 1021.27,799.96 1011.93,790.61 1011.93,790.51 1001.19,779.77 1001.19,653.55 1147.14,507.6 1456.6,507.6 1522.2,573.2 1711.72,573.2 1741.72,543.2 1758.2,543.2 1764.8,549.8 1764.8,569.8 1770,575 1785,575 1788.6,571.4 1788.6,548.4 1793.8,543.2 1807.1,543.2 R24.2@1810.75,546.85
RADAR_LVDS_FRCLKP: R22.2 U1.M14 | length 1201.3
  Top Layer w4: 1011.07,871.7 1011.07,893.17 1023.61,905.71 U1.M14@1023.62,906.07
  Top Layer w5.2: 1011.07,871.7 1011.07,804.18 1001.73,794.84 1001.73,794.74 990.99,784 990.99,649.32 1142.91,497.4 1460.83,497.4 1526.43,563 1707.5,563 1737.5,533 1789.6,533 R22.2@1810.75,511.85
RADAR_LVDS_VALIDM: R133.2
RADAR_LVDS_VALIDP: R131.2
RADAR_MCUCLKOUT: R62.2 R121.1 U1.N8 | length 1204.8
  Top Layer w4: U1.N8@998.03,1059.62 1007.57,1069.17 1007.57,1069.23 1023.06,1084.72 v2(1053.07,1084.72)
  L4 w4: v2(1053.07,1084.72) 1073.87,1063.92 1073.87,1021.56 1090.58,1004.86 1106.38,1004.86 1132.27,978.96 1132.27,971.61 1152.74,951.14 1152.74,924.07
  L4 w6: 1152.74,924.07 1152.74,849 1241.74,760 v2(1241.74,646) 1306.22,646 v2(1341.04,611.18)
  Bottom Layer w6: R121.1@1003.74,543.62 1009.92,549.8 1048.37,549.8 1088.74,590.17 1088.74,633.88 1104.34,649.48 1128.89,649.48 1142.37,662.96 1171.71,662.96 1188.67,646 v2(1241.74,646) ; v2(1341.04,611.18) 1341.04,644.78 1408.44,712.18 1408.44,730 1418.44,740 R62.2@1437.01,740
RADAR_MISO1: R12.2 U1.E14 | length 745.8
  Top Layer w4: v2(1200,666.9) 1205.7,666.9 1219.29,680.49 1219.29,830 1210.95,838.34 1210.95,867.33 1215.5,871.88 1215.5,893.32 U1.E14@1202.95,905.86
  Top Layer w6: v2(1532,507) 1532,484 1541,475 R12.2@1562.01,475
  L4 w5.98: v2(1200,666.9) 1200,615.62 1221.25,594.37 1308.83,594.37 1337.72,565.49 1473.51,565.49 1505.94,533.06
  L4 w6: 1505.94,533.06 v2(1532,507)
RADAR_MOSI1: R11.1 U1.D13 | length 925.2
  Top Layer w4: U1.D13@1228.54,931.45 1241.43,944.34 1241.43,952.52 v2(1256.07,967.17)
  Top Layer w5.98: v2(1495,461) 1516,440 R11.1@1562.01,440
  L4 w5.98: v2(1256.07,967.17) 1256.07,950.07 1198,892 1198,844 1332,710 1409.7,710 1575.71,544 1576,544 1576,480 1557,461 v2(1495,461)
RADAR_MSS_LOGGER: R31.2 U1.F14 | length 1364.8
  Top Layer w4: U1.F14@1177.16,906.07 1177.15,905.39 1189.87,892.67 ; 1190.28,892.26 1190.28,836.35 1202.29,824.35 1202.29,766.32 1183.59,747.62 1183.59,714.49 v2(1197.95,700.13)
  L4 w5.98: v2(1197.95,700.13) 1173.81,675.99 1173.81,658.19 1184.49,647.51 1184.49,609.2 1211.31,582.38 1303.85,582.38 1332.73,553.5 1449.86,553.5 1474.81,528.55 1474.81,441.19 1496.81,419.19 1663.19,419.19 1694.19,450.19 1798.18,450.19 1864.93,516.94 1926.93,516.94 1959.73,484.14 v2(1992.77,484.14)
  Bottom Layer w5.98: R31.2@1956.74,480 1988.63,480 v2(1992.77,484.14)
RADAR_NERR_OUT: R59.2 R93.1 R169.1 U1.N6 | length 3455.8
  Top Layer w4: v2(901.68,1143.86) 921.88,1123.66 985.16,1123.66 U1.N6@998.23,1110.59
  Top Layer w6: v4(1905,930) 1923.62,948.62 R169.1@1923.62,970
  L3 w6: v2(1202,408) 1219.3,425.3 1219.3,445.65 1229.43,455.79 1254.81,455.79 1285.2,425.39 1285.2,408.61 1351.01,342.8 1628.8,342.8 v2(1673,387)
  L4 w6: v2(901.68,1143.86) 901.68,1182.8 880.88,1203.6 818.48,1203.6 802.07,1220.01 736.99,1220.01 722,1235 722,1256 733,1267 791.93,1267 824.13,1234.8 878.6,1234.8 922.9,1279.1 1000.11,1279.1 1042.21,1237 1384.89,1237 1469.98,1151.91 1787.09,1151.91 1905,1034 v4(1905,930) 1905,796.22 1945,756.22 1945,725.38 1997.44,672.94 1997.44,642.44 v4(1980,625) 2023,582 2023,476 2010,463 1866,463 1811,408 1747,408 1726,387 v2(1673,387)
  Bottom Layer w6: v2(1202,408) 1202,374.34 R93.1@1208.23,368.11 ; v4(1980,625) 1995.03,640.03 1995.03,691.97 R59.2@1985,702.01
RADAR_NERRIN: R58.2 R150.1 U1.N7 | length 2250.4
  Top Layer w4: U1.N7@998.03,1085.21 1000.46,1085.21 v2(1018.77,1103.52)
  Top Layer w6: R150.1@1950,691.38 1972.99,668.38 v4(1972.99,657.01)
  L3 w6: v2(1018.77,1103.52) 989,1133.29 989,1479 1065,1555 1643,1555 1755,1443 1755,1071 1804,1022 1830.72,1022 1875.92,976.8 1875.92,852.56 1972.99,755.49 v4(1972.99,657.01)
  Bottom Layer w6: R58.2@1950,702.01 1950,680 v4(1972.99,657.01)
RADAR_NRST: C53.2 R42.1 R90.2 R91.2 R95.1 R168.1 U1.R3 | length 3576.1
  Top Layer w4: v2(855.59,1255) 875.59,1235 888.22,1235 935.65,1187.57 U1.R3@946.84,1187.57
  L4 w6: v2(855.59,1255) 875.79,1255 917.57,1296.78 1004.84,1296.78 1051.62,1250 1389.88,1250 1472.71,1167.17 1797.83,1167.17 1928,1037 1928,795.97 1967,756.97 1967,721 2047,641 2047,478 2018,449 1976,449 1959,432 1959,395 v4(1988,366) 2004.16,349.84 2004.16,239.64 1984.52,220 1920,220 1914.97,225.03 1783.03,225.03 1770.14,212.14 1727.14,212.14 1643.12,128.11 1418.79,128.11 1403.75,143.16 1285.16,143.16 v4(1253,111)
  Bottom Layer w6: R42.1@1956.74,410 1956.73,380.26 1971,366 v4(1988,366)
  Bottom Layer w8: R91.2@1020,216.38 1024.61,211.77 1127.23,211.77 1140,199 1181,199 1198.38,216.38 R90.2@1220,216.38 1220,173.62 C53.2@1228.62,165 1253,140.62 v4(1253,111) 1287.38,111 R168.1@1291.38,115 1295,115 1313.87,133.87 1313.87,140.25 R95.1@1338.62,165
RADAR_OSC_CLKOUT: R61.2 U1.A14 | length 483
  Top Layer w4: U1.A14@1305.31,905.86 1330.44,880.74 v2(1346,880.74)
  L4 w6: v2(1346,880.74) 1360.37,866.37 1508.25,866.37 1546.85,827.77 1546.85,754.85 v2(1522,730)
  Bottom Layer w6: R61.2@1437.01,705 1437.01,718.43 1440.85,722.27 1514.27,722.27 v2@1520.5,728.5
RADAR_PMIC_CLKOUT_SOP2: R63.2 R102.1 R165.1 U1.P9 | length 3494.2
  Top Layer w4: v2(700,1019) 700,1052 715.7,1067.7 715.7,1072.11 725.59,1082 858.59,1082 865.59,1075 865.59,1052 896.27,1021.32 960.14,1021.32 U1.P9@972.64,1033.82
  L3 w6: v2(700,1019) 725,1044 765,1044 784,1025 784,890.21 878.27,795.94 986.04,795.94 1001,780.98 1104.45,780.98 1138.97,746.46 1177.88,746.46 ; v2(1158.74,639.76) 1177.75,658.77 1177.75,746.33 1177.88,746.46 ; v4(1597.27,48.47) 1662.27,48.47 1693.79,80 1877,80 1926.2,129.2 1926.2,205.2 1837,294.4 1837,798 1738.48,896.52 1570.85,896.52 1537.6,863.27 1492.06,863.27 1453.74,824.95 v2(1453.74,812) 1419.28,812 1365.98,758.7 1190.12,758.7 1177.88,746.46
  Bottom Layer w6: R165.1@1120,623.62 1136.14,639.76 v2(1158.74,639.76) ; R102.1@1335.62,60 1365,89.38 1365,123.28 1397.72,156 1544,156 1570,130 1570,75.74 v4(1597.27,48.47) ; R63.2@1437.01,775 1437.01,795.27 v2(1453.74,812)
RADAR_QSPI_CS: R50.2 U1.P11 U2.1 | length 920.3
  Top Layer w4: 853.78,958.57 857.41,962.2 923.26,962.2 931.06,970 960.31,970 U1.P11@972.33,982.03
  Top Layer w6: R50.2@355,744.69 359,748.69 U2.1@359,789.76 359,803 346,816 346,969.22 357.78,981 365,981 v4(384,1000) ; v2(671.74,1000) 671.74,980.94 683.68,969 732.63,969 746.28,955.34 850.55,955.34 853.78,958.57
  Bottom Layer w6: v4@385,1000 524,1000 536,988 659.74,988 v2(671.74,1000)
RADAR_QSPI_D0: R45.2 U1.R13 | length 844.3
  Top Layer w4: 884.59,932.2 946.3,932.2 U1.R13@947.05,931.45
  Top Layer w6: R45.2@470,1102.99 470,1148 475,1153 491,1153 496,1148 496,1062 527,1031 527,981 536,972 543.8,972 549,977.2 549,1006.8 554.2,1012 569.8,1012 575,1006.8 575,954.2 580.2,949 595.8,949 601,954.2 601,984 607,990 619,990 626,983 626,974 668,932 718.71,932 731.51,919.2 866.71,919.2 879.71,932.2 884.59,932.2
RADAR_QSPI_D1: R46.1 U1.N12 | length 903.1
  Top Layer w4: 940.59,893.07 952.87,893.07 959.37,899.57 959.37,910.77 967.27,918.67 979.17,918.67 984.97,924.47 984.97,944.21 U1.N12@998.03,957.25
  Top Layer w6: R46.1@415,712.01 437.99,712.01 450,700 450,685 465,670 522,670 567,715 567,912 580,925 631.77,925 648.77,908 708.77,908 721.57,895.2 863.54,895.2 883.74,875 905.59,875 923.66,893.07 940.59,893.07
RADAR_QSPI_D2: R44.1 R47.1 U1.R14 | length 841.2
  Top Layer w6: R44.1@480,695.32 503.31,695.31 520,712.01 545.01,712.01 555,722 555,746 547,754 533.98,754 527.48,760.5 527.48,773.5 533.98,780 548.5,780 555,786.5 555,799.5 548.5,806 533,806 526.5,812.5 526.5,825.5 533,832 548.5,832 555,838.5 555,851.5 548.5,858 529.24,858 522.74,864.5 522.74,877.5 529.24,884 549,884 555,890 555,923 569,937 636.74,937 653.74,920 713.74,920 726.54,907.2 873.39,907.2 890.59,890 904.72,890 920.59,905.86 U1.R14@947.05,905.86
